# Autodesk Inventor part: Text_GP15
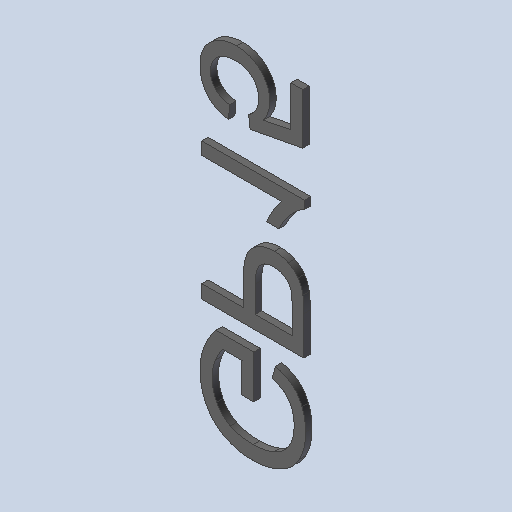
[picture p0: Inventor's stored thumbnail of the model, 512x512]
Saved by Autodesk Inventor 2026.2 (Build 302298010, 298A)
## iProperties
Created: 2026-10
Part Number: Text_GP15
Material: Générique
Document SubType Name: Modeling
Designer: mel
Density: 1 g/cm^3
Appearance: Par défaut
Author: mel
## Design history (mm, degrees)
feature "Base1"
feature "Base2"
feature "Base3"
feature "Base4"
node "Solide1"
node "Solide2"
node "Solide3"
node "Solide4"
